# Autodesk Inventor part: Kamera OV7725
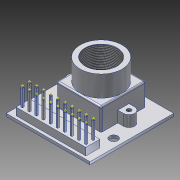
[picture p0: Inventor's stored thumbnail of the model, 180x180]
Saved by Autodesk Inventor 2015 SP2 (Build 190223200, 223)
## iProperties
Created: 2012-10
Part Number: Kamera OV7725
Material: Aluminium 6061
Document SubType Name: Modeling
Designer: rYan
Density: 2.71 g/cm^3
Mass: 9.47049 g
Surface Area: 37.4386 cm^2
Volume: 3.49464 cm^3
Appearance: Aluminium - flach
Author: rYan
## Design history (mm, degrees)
sketch "Skizze1"
  geometry: L1 (-15, 15)-(15, 15); L2 (15, 15)-(15, -15); L3 (15, -15)-(-15, -15); L4 (-15, -15)-(-15, 15); L5 (-21, 0)-(21, 0) reference; L6 (0, -21)-(0, 21) reference; 1 further point
  constraints: 8 end point, 2 parallel, 1 horizontal, 1 perpendicular, 2 other
  dimensions: "d0" = 30 distance of L1.start L1.end; "d1" = 30 distance of L1.end L2.end
extrude "Extrusion1" new body sketch "Skizze1" distance "d2" = 1; taper "d3" = 0 deg
sketch "Skizze2"
  geometry: L1 (-8, 12)-(8, 12); L2 (8, 12)-(8, -4); L3 (8, -4)-(-8, -4); L4 (-8, -4)-(-8, 12); L5 (0, -21)-(0, 21) reference; L6 (15, 15)-(-15, 15) reference; 1 further point
  constraints: 8 end point, 2 parallel, 1 horizontal, 1 perpendicular, 1 other
  dimensions: "d4" = 16 distance of L2.end L3.end; "d5" = 16 distance of L1.end L2.end; "d6" = 3 distance between parallel lines of L6 L1
extrude "Extrusion2" join sketch "Skizze2" distance "d7" = 8; taper "d8" = 0 deg
sketch "Skizze3"
  geometry: L1 (8, 12)-(-8, 12) reference; L2 (-8, 12)-(-8, -4) reference; L3 (8, -4)-(8, 12) reference; L4 (-8, -4)-(8, -4) reference; L5 (0, 12)-(0, -4); L6 (8, 4)-(-8, 4); C1 r 7.5 at (0, 4); 2 further points
  constraints: 5 midpoint, 4 end point, 1 centre point, 1 coincident
  dimensions: "d9" = 15 diameter of C1
extrude "Extrusion3" join sketch "Skizze3" distance "d10" = 7.5; taper "d11" = 0 deg
sketch "Skizze4"
  geometry: L1 (-8, -4)-(-8, 12) reference; L2 (-15, 15)-(-15, -15) reference; L3 (-8, 4)-(-15, 4); L4 (8, 12)-(8, -4) reference; L5 (15, -15)-(15, 15) reference; L6 (8, 4)-(15, 4); L7 (-10, 6)-(-8, 6); L8 (-10, 2)-(-8, 2); L9 (10, 6)-(8, 6); L10 (10, 2)-(8, 2); A1 r 2 centre (-10, 4) between (-10, 6) and (-10, 2); A2 r 2 centre (10, 4) between (10, 2) and (10, 6); 1 further point
  constraints: 12 end point, 8 point on line, 4 point on circle, 4 tangent, 3 parallel, 3 perpendicular, 2 centre point, 2 midpoint
  dimensions: "d12" = 4 diameter of A1; "d13" = 4 diameter of A2; "d16" = 2 distance from line of L1 A1.centre; "d17" = 2 distance from line of L4 A2.centre
extrude "Extrusion4" join sketch "Skizze4" distance "d18" = 4; taper "d19" = 0 deg
sketch "Skizze5"
  geometry: A1 r 2 centre (-10, 4) between (-10, 6) and (-10, 2) reference; A2 r 2 centre (10, 4) between (10, 2) and (10, 6) reference; 3 further points
  constraints: 2 coincident
hole "Bohrung1" sketch "Skizze5" at (-10, 4), (10, 4) diameter "d20" = 1.567; stored, may be unused: countersink angle "d24" = 90 deg, drill point angle "d26" = 118 deg; dims "d21" = 6, "d22" = 4, "d23" = 2, "d25" = 8
sketch "Skizze6"
  geometry: C1 r 7.5 at (0, 0) reference; 2 further points
  constraints: 1 coincident
hole "Bohrung2" sketch "Skizze6" at (0, 0) diameter "d27" = 11.459; stored, may be unused: countersink angle "d31" = 90 deg, drill point angle "d33" = 0 deg; dims "d28" = 8, "d29" = 4, "d30" = 2, "d32" = 12
sketch "Skizze7"
  geometry: L1 (-12.5, -9)-(12.5, -9); L2 (12.5, -9)-(12.5, -14); L3 (12.5, -14)-(-12.5, -14); L4 (-12.5, -14)-(-12.5, -9); L5 (0, -21)-(0, 21); L6 (-21, 0)-(21, 0); 1 further point
  constraints: 12 end point, 2 parallel, 1 horizontal, 1 perpendicular, 1 other
  dimensions: "d34" = 25 distance of L2.end L3.end; "d35" = 5 distance of L1.end L2.end; "d36" = 9 distance between parallel lines of L1 L6
extrude "Extrusion5" join sketch "Skizze7" distance "d37" = 2.7; taper "d38" = 0 deg
sketch "Skizze8"
  geometry: L1 (-11.7, -10)-(-11.1, -10); L2 (-11.1, -10)-(-11.1, -10.6); L3 (-11.1, -10.6)-(-11.7, -10.6); L4 (-11.7, -10.6)-(-11.7, -10); L5 (12.5, -9)-(-12.5, -9) reference; L6 (-12.5, -9)-(-12.5, -14) reference; L7 (-12.5, -14)-(12.5, -14) reference; L8 (12.5, -14)-(12.5, -9) reference; 1 further point
  constraints: 8 end point, 2 parallel, 1 horizontal, 1 perpendicular
  dimensions: "d39" = 0.6 distance of L2.end L3.end; "d40" = 0.6 distance of L1.end L2.end; "d41" = 1 distance between parallel lines of L5 L1; "d42" = 0.8 distance between parallel lines of L6 L4
extrude "Extrusion6" join sketch "Skizze8" distance "d51" = 6.5; taper "d52" = 0 deg
chamfer "Fase1" distance "d53" = 0.15; stored, may be unused: second distance "d54" = 2, angle "d55" = 70 deg
fillet "Rundung1" dims "d62" = 0.5
sketch "Skizze9"
  geometry: L1 (15, 15)-(-15, 15) reference; L2 (-15, 15)-(-15, -15) reference; L3 (15, -15)-(15, 15) reference; 3 further points
  dimensions: "d63" = 3 distance from line of L1 point (-12, 12); "d64" = 3 distance from line of L2 point (-12, 12); "d65" = 18.5 distance from line of point (12, -3.5) L1; "d66" = 3 distance from line of L3 point (12, -3.5)
hole "Bohrung3" sketch "Skizze9" at (-12, 12), (12, -3.5) diameter "d67" = 3; stored, may be unused: countersink angle "d71" = 90 deg, drill point angle "d73" = 118 deg; dims "d68" = 6, "d69" = 4, "d70" = 2, "d72" = 8
workpoint "Arbeitspunkt2"
node "1"
node "2"
node "3"
node "4"
node "5"
node "6"
node "7"
node "8"
node "9"
node "10"
node "11"
node "12"
node "13"
node "14"
node "15"
node "16"
node "17"
node "18"
node "19"
node "20"
node "Volumenkörper1"
pattern_linear "Rechteckige Anordnung1" dims "d58" = 2.54, "d61" = 2.54
node "Projizierte Kontur1"
